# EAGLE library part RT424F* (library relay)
Power PCB Relay polarized bistable version SCHRACK 2 pole 8 A Source: http://www.schrack.com/.. 5843.pdf
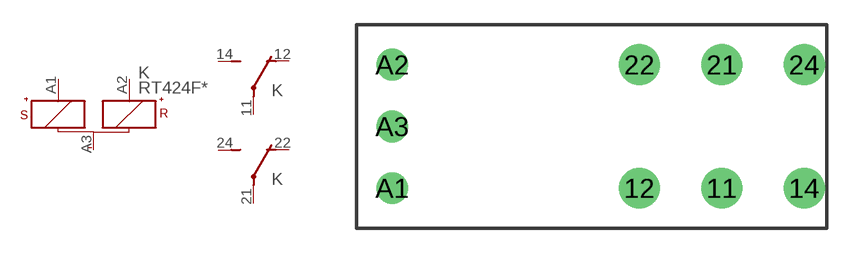
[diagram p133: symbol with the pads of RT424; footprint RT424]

Designator prefix K; gates 1=+KS+KR- 2=U 3=U

## RT424F054 (OC_FARNELL: unknown; OC_NEWARK: unknown), RT424F064 (OC_FARNELL: unknown; OC_NEWARK: unknown), RT424F124 (OC_FARNELL: unknown; OC_NEWARK: unknown), RT424F244 (OC_FARNELL: unknown; OC_NEWARK: unknown)  [RT424]
11  2:P  pas
12  2:O  pas
14  2:S  pas
21  3:P  pas
22  3:O  pas
24  3:S  pas
A1  1:S+  pas
A2  1:R+  pas
A3  1:-  pas

## Footprint RT424 (pad centres in mm)
Power PCB Relay polarized bistable version SCHRACK 2 pole 8 A Source: http://www.schrack.com/.. 5843.pdf
drill 1.3 pad 2.5 round: 11 7.56,-3.78; 12 2.52,-3.78; 14 12.6,-3.78; 21 7.56,3.78; 22 2.52,3.78; 24 12.6,3.78
drill 1.3 round: A1 -12.6,-3.78; A2 -12.6,3.78; A3 -12.6,0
